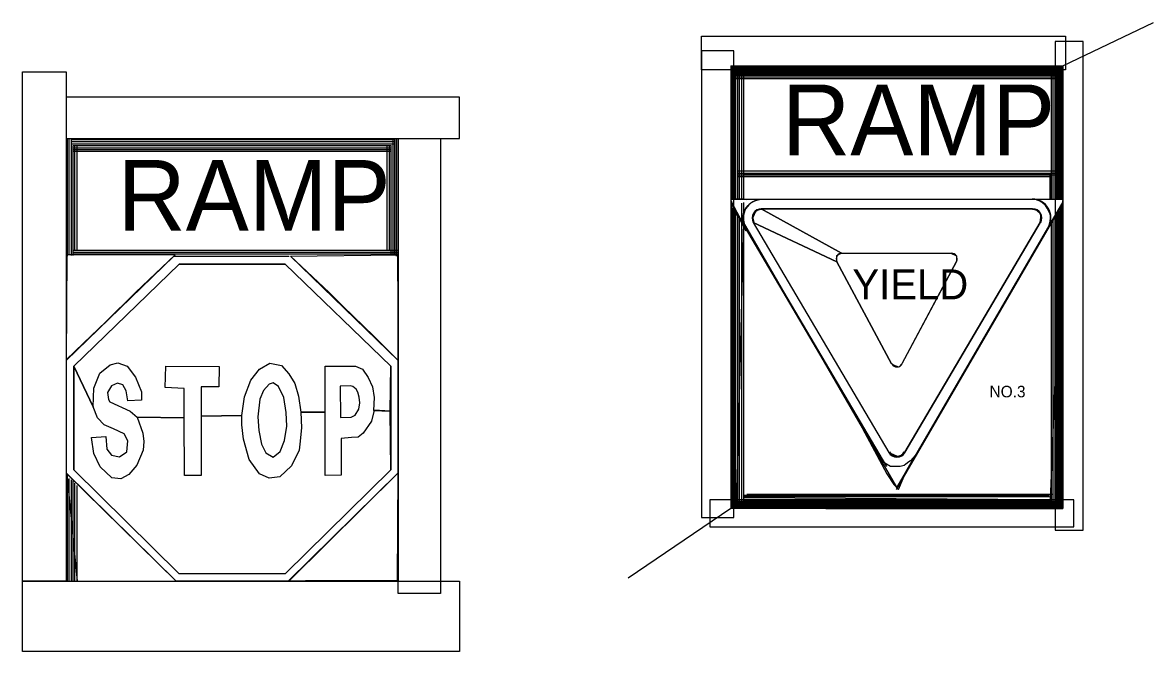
# Model space of a CAD drawing. Extents: x -0.308 to 0.195, y -0.006 to 0.263.
# Drawn here: x -0.3077 to -0.0625, y 0.0893 to 0.2256 of the extents above; entities that cross this region are included whole.
import ezdxf

# ---------------------------------------------------------------- set-up
doc = ezdxf.new("R2010")
doc.units = 0
doc.layers.add('3', color=7, linetype='Continuous')

msp = doc.modelspace()

# ---------------------------------------------------------------- linework, layer by layer
at = {"layer": '3'}
for p, q in [((-0.082125, 0.21625), (-0.06246942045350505, 0.22562920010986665)), ((-0.154125, 0.21625), (-0.082125, 0.21625)), ((-0.154125, 0.21625), (-0.154125, 0.12025)), ((-0.154125, 0.216), (-0.082125, 0.216)), ((-0.153875, 0.1875), (-0.153875, 0.21625)), ((-0.153625, 0.1875), (-0.153625, 0.21625)), ((-0.15325, 0.1875), (-0.15325, 0.21625)), ((-0.153, 0.1875), (-0.153, 0.21625)), ((-0.152625, 0.1875), (-0.152625, 0.21625)), ((-0.15225, 0.1875), (-0.15225, 0.21625)), ((-0.15175, 0.1875), (-0.15175, 0.21625)), ((-0.151375, 0.21625), (-0.151375, 0.1875)), ((-0.082125, 0.21625), (-0.082125, 0.12025)), ((-0.154125, 0.21575), (-0.082125, 0.21575)), ((-0.154125, 0.2155), (-0.082125, 0.2155)), ((-0.154125, 0.21525), (-0.082125, 0.21525)), ((-0.154125, 0.215), (-0.082125, 0.215)), ((-0.154125, 0.21475), (-0.082125, 0.21475)), ((-0.154125, 0.2145), (-0.082125, 0.2145)), ((-0.154125, 0.21425), (-0.082125, 0.21425)), ((-0.154125, 0.213875), (-0.082125, 0.213875)), ((-0.154125, 0.2135), (-0.082125, 0.2135)), ((-0.084625, 0.21475), (-0.084625, 0.1875)), ((-0.08425, 0.21475), (-0.08425, 0.1875)), ((-0.083875, 0.21475), (-0.083875, 0.187375)), ((-0.083625, 0.21475), (-0.083625, 0.187375)), ((-0.083375, 0.21475), (-0.083375, 0.187375)), ((-0.083125, 0.21475), (-0.083125, 0.187375)), ((-0.082875, 0.21475), (-0.082875, 0.1875)), ((-0.082625, 0.21475), (-0.082625, 0.187375)), ((-0.082375, 0.21475), (-0.082375, 0.1875)), ((-0.29825, 0.2005), (-0.22625, 0.2005)), ((-0.29825, 0.2005), (-0.29825, 0.1045)), ((-0.298, 0.17500000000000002), (-0.298, 0.200375)), ((-0.29762500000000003, 0.17525000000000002), (-0.29762500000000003, 0.200375)), ((-0.29712500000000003, 0.175125), (-0.29712500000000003, 0.200375)), ((-0.297, 0.20025), (-0.227125, 0.20025)), ((-0.297, 0.199875), (-0.227125, 0.199875)), ((-0.297, 0.199375), (-0.227125, 0.199375)), ((-0.29675, 0.199), (-0.22775, 0.199)), ((-0.29675, 0.175125), (-0.29675, 0.199)), ((-0.296375, 0.17625), (-0.296375, 0.199)), ((-0.295875, 0.17625), (-0.295875, 0.199)), ((-0.228625, 0.17625), (-0.228625, 0.199)), ((-0.228125, 0.17625), (-0.228125, 0.199)), ((-0.22775, 0.175125), (-0.22775, 0.199)), ((-0.227375, 0.175125), (-0.227375, 0.200375)), ((-0.227, 0.17525000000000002), (-0.227, 0.200375)), ((-0.226625, 0.17500000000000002), (-0.226625, 0.200375)), ((-0.22625, 0.2005), (-0.22625, 0.1045)), ((-0.29675, 0.1985), (-0.22775, 0.1985)), ((-0.29675, 0.198125), (-0.22775, 0.198125)), ((-0.29675, 0.19775), (-0.22775, 0.19775)), ((-0.152625, 0.1935), (-0.083625, 0.1935)), ((-0.152625, 0.193), (-0.083625, 0.193)), ((-0.152625, 0.192625), (-0.083625, 0.192625)), ((-0.152625, 0.19225), (-0.085, 0.19225)), ((-0.154125, 0.187375), (-0.151375, 0.187375)), ((-0.154125, 0.187), (-0.150875, 0.180875)), ((-0.15175, 0.12175), (-0.15175, 0.1865)), ((-0.151375, 0.187375), (-0.08225, 0.187375)), ((-0.151375, 0.186625), (-0.151375, 0.184375)), ((-0.15075, 0.18725), (-0.085, 0.187375)), ((-0.082125, 0.18675), (-0.11812500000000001, 0.124875)), ((-0.154, 0.186375), (-0.150875, 0.1805)), ((-0.153875, 0.12175), (-0.153875, 0.186)), ((-0.153625, 0.12175), (-0.153625, 0.1855)), ((-0.15325, 0.12175), (-0.15325, 0.18475)), ((-0.153, 0.12175), (-0.153, 0.18425)), ((-0.152625, 0.12175), (-0.152625, 0.184)), ((-0.1475, 0.18525), (-0.08875, 0.18525)), ((-0.08225, 0.18625), (-0.11825000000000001, 0.124375)), ((-0.083375, 0.184125), (-0.083375, 0.12175)), ((-0.083125, 0.184625), (-0.083125, 0.12175)), ((-0.082875, 0.184875), (-0.082875, 0.12175)), ((-0.082625, 0.185375), (-0.082625, 0.12175)), ((-0.082375, 0.186), (-0.082375, 0.12175)), ((-0.15225, 0.12175), (-0.15225, 0.183625)), ((-0.151375, 0.182375), (-0.151375, 0.12175)), ((-0.14925, 0.18225), (-0.11987500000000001, 0.132375)), ((-0.08700000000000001, 0.18225), (-0.116375, 0.1325)), ((-0.084625, 0.182125), (-0.084625, 0.12175)), ((-0.08425, 0.182625), (-0.08425, 0.12175)), ((-0.083875, 0.1835), (-0.083875, 0.12175)), ((-0.083625, 0.18375), (-0.083625, 0.12175)), ((-0.151, 0.181375), (-0.120375, 0.129375)), ((-0.151, 0.181125), (-0.121625, 0.13125)), ((-0.274875, 0.17500000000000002), (-0.29825, 0.152375)), ((-0.29675, 0.17625), (-0.22625, 0.17625)), ((-0.29675, 0.175875), (-0.22625, 0.175875)), ((-0.29675, 0.17550000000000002), (-0.22625, 0.17550000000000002)), ((-0.274875, 0.17500000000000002), (-0.249875, 0.17500000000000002)), ((-0.249625, 0.17500000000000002), (-0.22625, 0.152375)), ((-0.130125, 0.175625), (-0.106375, 0.175625)), ((-0.27375, 0.17325000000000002), (-0.296625, 0.151125)), ((-0.27375, 0.17325000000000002), (-0.25075000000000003, 0.17325000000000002)), ((-0.25075000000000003, 0.17325000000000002), (-0.227875, 0.151125)), ((-0.131125, 0.17375000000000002), (-0.11925000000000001, 0.151625)), ((-0.10525, 0.17375000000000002), (-0.117, 0.151625)), ((-0.296625, 0.128625), (-0.296625, 0.151125)), ((-0.227875, 0.151125), (-0.227875, 0.128625)), ((-0.29825, 0.128), (-0.274375, 0.1045)), ((-0.22625, 0.128), (-0.250125, 0.1045)), ((-0.298, 0.1045), (-0.298, 0.127)), ((-0.29762500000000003, 0.1045), (-0.29762500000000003, 0.12675)), ((-0.29712500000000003, 0.1045), (-0.29712500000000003, 0.1265)), ((-0.29675, 0.1045), (-0.29675, 0.12625)), ((-0.296375, 0.1045), (-0.296375, 0.12575)), ((-0.295875, 0.1045), (-0.295875, 0.12525)), ((-0.15125, 0.123125), (-0.085, 0.123125)), ((-0.15125, 0.122875), (-0.085, 0.122875)), ((-0.15125, 0.122625), (-0.08525, 0.12225)), ((-0.150625, 0.123375), (-0.084375, 0.123375)), ((-0.154125, 0.12025), (-0.17638894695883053, 0.10515020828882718)), ((-0.082125, 0.12175), (-0.154125, 0.12175)), ((-0.082125, 0.1215), (-0.154125, 0.1215)), ((-0.082125, 0.12125), (-0.154125, 0.12125)), ((-0.082125, 0.121), (-0.154125, 0.121)), ((-0.082125, 0.12075), (-0.154125, 0.12075)), ((-0.082125, 0.1205), (-0.154125, 0.1205)), ((-0.082125, 0.12025), (-0.154125, 0.12025)), ((-0.15125, 0.122125), (-0.085, 0.122125)), ((-0.1335, 0.12025), (-0.082125, 0.12025)), ((-0.22625, 0.1045), (-0.274375, 0.1045)), ((-0.274375, 0.1045), (-0.22625, 0.1045))]:
    msp.add_line(p, q, dxfattribs=at)
for points in [[(-0.0815316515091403, 0.21541911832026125), (-0.16050375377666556, 0.21541911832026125), (-0.16050375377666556, 0.22267962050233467), (-0.0815316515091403, 0.22267962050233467)], [(-0.08380096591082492, 0.11558718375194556), (-0.07767381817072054, 0.11558718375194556), (-0.07767381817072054, 0.22154516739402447), (-0.08380096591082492, 0.22154516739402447)], [(-0.15346888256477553, 0.2195031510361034), (-0.16050375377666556, 0.2195031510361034), (-0.16050375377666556, 0.11830987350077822), (-0.15346888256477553, 0.11830987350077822)], [(-0.29825, 0.1045), (-0.30770256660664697, 0.1045), (-0.30770256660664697, 0.21497738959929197), (-0.29825, 0.21497738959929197)], [(-0.29825, 0.2005), (-0.21295770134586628, 0.2005), (-0.21295770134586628, 0.20942854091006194), (-0.29825, 0.20942854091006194)], [(-0.22625, 0.2005), (-0.21705608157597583, 0.2005), (-0.21705608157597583, 0.10182913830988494), (-0.22625, 0.10182913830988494)], [(-0.151375, 0.187375), (-0.084875, 0.187375), (-0.084875, 0.19275), (-0.151375, 0.19275)], [(-0.15125, 0.187375), (-0.151875, 0.187375), (-0.154, 0.1875), (-0.154125, 0.187125), (-0.152875, 0.184), (-0.1515, 0.182375), (-0.151375, 0.1825), (-0.1515, 0.183125), (-0.1515, 0.18325), (-0.151375, 0.18425), (-0.151125, 0.184875), (-0.150875, 0.185375), (-0.150375, 0.186), (-0.149625, 0.186625), (-0.148875, 0.187), (-0.148, 0.18725)], [(-0.085, 0.187375), (-0.082125, 0.187375), (-0.08225, 0.18625), (-0.08325, 0.184625), (-0.083625, 0.184125), (-0.08525, 0.181125), (-0.084875, 0.1825), (-0.08475, 0.183375), (-0.08475, 0.183625), (-0.084875, 0.184125), (-0.085125, 0.18475), (-0.0855, 0.185375), (-0.085875, 0.186), (-0.08662500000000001, 0.186625), (-0.08725000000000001, 0.187), (-0.08825, 0.187375)], [(-0.151375, 0.182375), (-0.152875, 0.1215), (-0.14775, 0.122125), (-0.08475, 0.122), (-0.08225, 0.18625), (-0.11812500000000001, 0.124875)], [(-0.1475, 0.18525), (-0.14868589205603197, 0.1848315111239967), (-0.14941818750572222, 0.1832550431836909), (-0.14925, 0.18225), (-0.131125, 0.17375000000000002), (-0.1311410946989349, 0.17511029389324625), (-0.13063774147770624, 0.175445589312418), (-0.130125, 0.175625)], [(-0.1475, 0.18525), (-0.130125, 0.175625), (-0.106375, 0.175625), (-0.10519500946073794, 0.1750455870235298), (-0.1051622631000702, 0.17380331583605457), (-0.117, 0.151625), (-0.11770788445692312, 0.1509044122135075), (-0.11882510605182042, 0.151351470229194), (-0.11925000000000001, 0.151625), (-0.131125, 0.17375000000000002), (-0.14925, 0.18225), (-0.11987500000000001, 0.132375), (-0.11770788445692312, 0.13145735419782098), (-0.11681410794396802, 0.13212794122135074), (-0.116375, 0.1325), (-0.08700000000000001, 0.18225), (-0.08679935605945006, 0.1840153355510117), (-0.08776636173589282, 0.1848808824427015), (-0.08875, 0.18525)], [(-0.274625, 0.17525000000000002), (-0.29812500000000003, 0.17525000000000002), (-0.29825, 0.1525), (-0.2945, 0.156125), (-0.289625, 0.16075), (-0.28325, 0.167125)], [(-0.249625, 0.17500000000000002), (-0.226375, 0.17525000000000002), (-0.22625, 0.152375), (-0.2315, 0.15762500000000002), (-0.23825000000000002, 0.164125), (-0.24125, 0.167125)], [(-0.296625, 0.151125), (-0.29240067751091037, 0.1423280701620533), (-0.29228121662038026, 0.14638950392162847), (-0.29096716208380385, 0.1496147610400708), (-0.28869743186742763, 0.15140657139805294), (-0.28702499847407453, 0.15188438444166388), (-0.28499419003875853, 0.15116766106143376), (-0.2832022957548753, 0.14877858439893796), (-0.2818882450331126, 0.1455533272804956), (-0.2818882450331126, 0.1437615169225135), (-0.2848747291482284, 0.14364206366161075), (-0.285233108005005, 0.1457922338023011), (-0.28594986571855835, 0.14710622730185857), (-0.28714445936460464, 0.1474645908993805), (-0.28845851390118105, 0.1468673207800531), (-0.28929472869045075, 0.14543387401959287), (-0.2890558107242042, 0.14388097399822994), (-0.2888168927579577, 0.1434031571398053), (-0.28439689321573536, 0.1413724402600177), (-0.2828439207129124, 0.14005844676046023), (-0.27268986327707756, 0.1399389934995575), (-0.27268986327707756, 0.14627005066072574), (-0.27675148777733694, 0.14650895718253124), (-0.2766320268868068, 0.15116766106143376), (-0.26504445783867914, 0.15104820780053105), (-0.2651639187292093, 0.14662841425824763), (-0.26898662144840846, 0.14662841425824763), (-0.26898662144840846, 0.1402973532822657), (-0.26014662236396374, 0.14041681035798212), (-0.25954932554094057, 0.1444782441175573), (-0.25823527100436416, 0.14806186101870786), (-0.25632391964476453, 0.15045093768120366), (-0.2540541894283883, 0.15176493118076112), (-0.25154554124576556, 0.1512871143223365), (-0.2499925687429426, 0.14949530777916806), (-0.2486785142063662, 0.14734513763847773), (-0.24784229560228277, 0.14459769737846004), (-0.24736445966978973, 0.14113353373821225), (-0.242108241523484, 0.14113353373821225), (-0.242108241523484, 0.15116766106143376), (-0.2355379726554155, 0.15116766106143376), (-0.23398500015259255, 0.15045093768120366), (-0.23279040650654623, 0.14865913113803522), (-0.2318347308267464, 0.14662841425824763), (-0.2314763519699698, 0.14435878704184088), (-0.2315958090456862, 0.14149189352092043), (-0.22801202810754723, 0.1413724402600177), (-0.227875, 0.151125), (-0.25075000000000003, 0.17325000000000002), (-0.27375, 0.17325000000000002)], [(-0.296625, 0.151125), (-0.296625, 0.128625), (-0.2738470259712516, 0.1061872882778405), (-0.2507032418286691, 0.1061872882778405), (-0.227875, 0.128625), (-0.22801202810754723, 0.1413724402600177), (-0.2314763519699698, 0.1416113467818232), (-0.23207364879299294, 0.13922227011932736), (-0.23386553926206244, 0.1365942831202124), (-0.23494067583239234, 0.13575810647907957), (-0.2363741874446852, 0.1356386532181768), (-0.2386313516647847, 0.1354428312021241), (-0.23864391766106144, 0.12751578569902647), (-0.242108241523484, 0.12739633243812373), (-0.242108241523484, 0.14113353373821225), (-0.24736445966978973, 0.14113353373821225), (-0.24724499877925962, 0.13778882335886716), (-0.24760337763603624, 0.1342052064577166), (-0.24772283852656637, 0.13289121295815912), (-0.24939527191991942, 0.12954650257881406), (-0.2519039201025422, 0.12715742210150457), (-0.2542208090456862, 0.12684215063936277), (-0.25632391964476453, 0.12775469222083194), (-0.25859364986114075, 0.13086049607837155), (-0.25978824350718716, 0.13528028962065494), (-0.26014662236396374, 0.13838609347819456), (-0.26014662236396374, 0.14041681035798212), (-0.26898662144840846, 0.1402973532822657), (-0.26898662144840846, 0.12739633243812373), (-0.27257040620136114, 0.12739633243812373), (-0.27268986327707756, 0.1399389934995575), (-0.2828439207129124, 0.14005844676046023), (-0.2816493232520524, 0.1365942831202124), (-0.28141040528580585, 0.13480247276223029), (-0.2815298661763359, 0.13289121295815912), (-0.2829633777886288, 0.1296659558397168), (-0.2846358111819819, 0.1276352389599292), (-0.28642770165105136, 0.1266796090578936), (-0.28833905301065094, 0.1269185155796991), (-0.29084770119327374, 0.1293075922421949), (-0.29228121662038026, 0.13217448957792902), (-0.2927590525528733, 0.1356386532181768), (-0.28965310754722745, 0.1358775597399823), (-0.28941418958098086, 0.13313011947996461), (-0.28845851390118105, 0.13181612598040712), (-0.2866666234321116, 0.13145776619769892), (-0.28511364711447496, 0.13253284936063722), (-0.2848747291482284, 0.13492192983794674), (-0.28571094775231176, 0.13647482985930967), (-0.2879806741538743, 0.137549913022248), (-0.29001148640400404, 0.13838609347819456), (-0.2914450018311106, 0.1399389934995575), (-0.29240067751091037, 0.1423280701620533)], [(-0.2562250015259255, 0.1439837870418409), (-0.25670500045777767, 0.1401640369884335), (-0.25649499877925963, 0.1372165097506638), (-0.2559250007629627, 0.13423890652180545), (-0.2549349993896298, 0.13234406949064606), (-0.253375, 0.13141169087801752), (-0.251875, 0.1326448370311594), (-0.250914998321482, 0.13499082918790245), (-0.2504349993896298, 0.13814889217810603), (-0.2505249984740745, 0.14109641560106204), (-0.2510650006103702, 0.14434471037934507), (-0.25223500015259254, 0.14675085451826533), (-0.253375, 0.1475328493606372), (-0.2542449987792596, 0.1472621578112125), (-0.2554450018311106, 0.14587862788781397)], [(-0.2388150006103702, 0.14679308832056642), (-0.2387850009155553, 0.14002581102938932), (-0.23644500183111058, 0.14005588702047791), (-0.23557499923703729, 0.1404769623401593), (-0.23479499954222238, 0.14183041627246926), (-0.234585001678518, 0.14318387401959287), (-0.23470500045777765, 0.14441702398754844), (-0.2350050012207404, 0.14552986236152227), (-0.2353950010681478, 0.1461614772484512), (-0.2361150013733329, 0.14670285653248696), (-0.2366549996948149, 0.1468532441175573)], [(-0.12025, 0.12775), (-0.11875000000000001, 0.1255), (-0.11775000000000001, 0.124375), (-0.1165, 0.12725), (-0.116125, 0.12825), (-0.114125, 0.13175), (-0.115125, 0.130625), (-0.1155, 0.130375), (-0.116125, 0.129875), (-0.1165, 0.129625), (-0.11737500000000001, 0.129375), (-0.11812500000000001, 0.129375), (-0.11950000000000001, 0.129375), (-0.120375, 0.129875), (-0.121125, 0.130375), (-0.12725, 0.14075000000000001)], [(-0.29812500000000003, 0.12775), (-0.295875, 0.1045), (-0.274375, 0.1045)], [(-0.246375, 0.104625), (-0.226375, 0.104625), (-0.22625, 0.128), (-0.249625, 0.104875), (-0.25, 0.1045)], [(-0.15868830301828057, 0.11626785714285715), (-0.07971620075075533, 0.11626785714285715), (-0.07971620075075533, 0.12216701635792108), (-0.15868830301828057, 0.12216701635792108)], [(-0.30770256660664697, 0.1045), (-0.21295770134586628, 0.1045), (-0.21295770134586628, 0.0892839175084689), (-0.30770256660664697, 0.0892839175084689)]]:
    msp.add_lwpolyline(points, close=True, dxfattribs=at)
for centre, radius, start, end in [((-0.14739617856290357, 0.18326176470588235), 0.004, 90, 208.1237361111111), ((-0.08875628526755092, 0.18333877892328), 0.004048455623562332, 331.0033472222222, 89.12708333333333), ((-0.1474835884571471, 0.18326176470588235), 0.002, 90, 208.11320833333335), ((-0.1474835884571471, 0.18326176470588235), 0.0018580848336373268, 90, 208.11320833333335), ((-0.08865562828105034, 0.18326176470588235), 0.002, 331.8867916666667, 90), ((-0.08865562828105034, 0.18326176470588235), 0.0018613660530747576, 331.8867916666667, 90), ((-0.13000752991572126, 0.17438676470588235), 0.00125, 90.00000000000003, 207.55281111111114), ((-0.10626774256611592, 0.17438676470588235), 0.00125, 332.17590277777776, 90), ((-0.11805724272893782, 0.15221323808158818), 0.00125, 207.29957222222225, 332.1759027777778), ((-0.11809911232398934, 0.1333831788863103), 0.002, 208.4956388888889, 332.3005277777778), ((-0.11809911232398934, 0.1333831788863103), 0.0017991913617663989, 208.4956388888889, 332.3005277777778)]:
    msp.add_arc(centre, radius, start, end, dxfattribs=at)

# ---------------------------------------------------------------- texts
for s, height, p in [('RAMP', 0.01533, (-0.14300000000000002, 0.196875)), ('RAMP', 0.01533, (-0.287125, 0.1805)), ('YIELD', 0.006500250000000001, (-0.12775, 0.165625)), ('NO.3', 0.0024997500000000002, (-0.098, 0.144375))]:
    msp.add_text(s, height=height, dxfattribs=at).set_placement(p)

doc.saveas('drawing.dxf')
